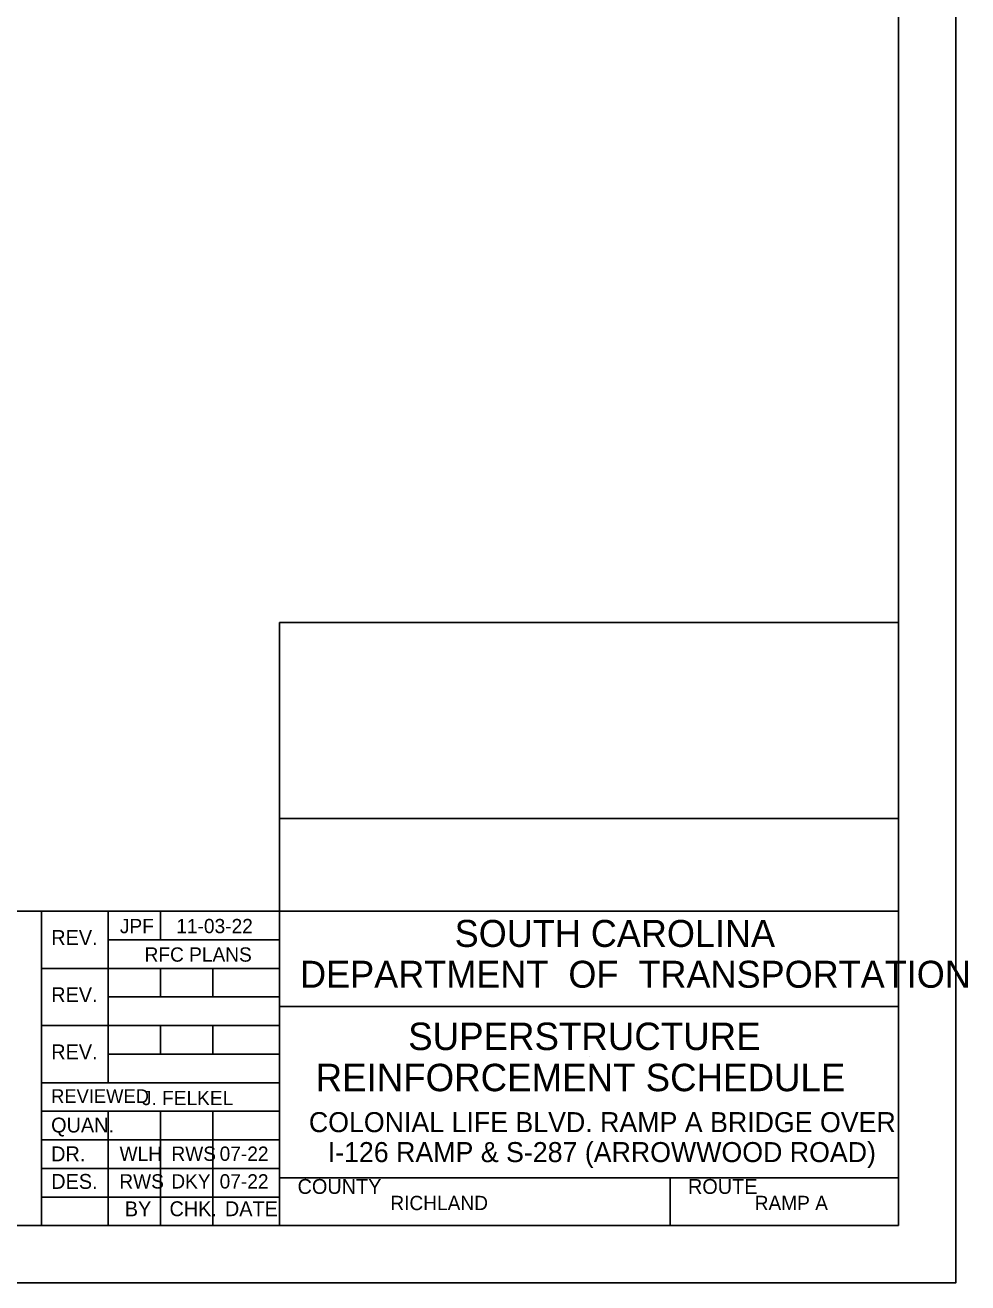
# Model space of a CAD drawing. Extents: x -125.5 to -89.4, y -5.1 to 16.9.
# Drawn here: x -97.68 to -89.43, y -5.07 to 5.93 of the extents above; entities that cross this region are included whole.
import ezdxf

# ---------------------------------------------------------------- set-up
doc = ezdxf.new("R2010")
doc.units = 0
for name, color, linetype in [('BR_BORDER LINES', 7, 'Continuous'), ('BR_TEXT', 7, 'Continuous'), ('Level 31', 7, 'Continuous')]:
    doc.layers.add(name, color=color, linetype=linetype)

msp = doc.modelspace()

# ---------------------------------------------------------------- linework, layer by layer
at = {"layer": 'BR_BORDER LINES'}
for p, q in [((-90.033, -4.566), (-90.033, 16.434)), ((-95.45, -4.566), (-95.45, 0.71)), ((-95.45, 0.71), (-90.033, 0.71)), ((-95.45, -1.004), (-90.033, -1.004)), ((-102.899, -1.816), (-97.534, -1.816)), ((-97.534, -4.566), (-97.534, -1.816)), ((-97.534, -1.816), (-90.033, -1.816)), ((-96.95, -1.816), (-96.95, -3.316)), ((-96.492, -2.066), (-96.492, -1.816)), ((-96.95, -2.066), (-95.45, -2.066)), ((-97.534, -2.316), (-95.45, -2.316)), ((-96.492, -2.566), (-96.492, -2.316)), ((-96.034, -2.566), (-96.034, -2.316)), ((-96.95, -2.566), (-95.45, -2.566)), ((-95.45, -2.649), (-95.45, -2.649)), ((-95.45, -2.649), (-90.033, -2.649)), ((-97.534, -2.816), (-95.45, -2.816)), ((-96.492, -3.066), (-96.492, -2.816)), ((-96.034, -3.066), (-96.034, -2.816)), ((-96.95, -3.066), (-95.45, -3.066)), ((-97.534, -3.316), (-95.45, -3.316)), ((-97.534, -3.566), (-95.45, -3.566)), ((-96.95, -3.566), (-96.95, -4.566)), ((-96.492, -3.566), (-96.492, -4.566)), ((-96.034, -3.566), (-96.034, -4.566)), ((-97.534, -3.816), (-95.45, -3.816)), ((-97.534, -4.066), (-95.45, -4.066)), ((-95.45, -4.149), (-90.033, -4.149)), ((-95.353, -4.149), (-90.033, -4.149)), ((-92.033, -4.566), (-92.033, -4.149)), ((-97.534, -4.316), (-95.45, -4.316)), ((-123.699, -4.566), (-90.033, -4.566))]:
    msp.add_line(p, q, dxfattribs=at)
at = {"layer": 'Level 31'}
msp.add_line((-92.742, -3.09), (-92.742, -3.09), dxfattribs=at)
msp.add_line((-92.742, -3.09), (-92.742, -3.09), dxfattribs=at)
msp.add_lwpolyline([(-125.533, 16.934), (-125.533, -5.066), (-89.533, -5.066), (-89.533, 16.934)], dxfattribs=at)

# ---------------------------------------------------------------- texts
at = {"layer": 'BR_TEXT'}
for s, height, p in [('JPF', 0.125, (-96.848, -2.008)), ('11-03-22', 0.125, (-96.354, -2.008)), ('SOUTH CAROLINA', 0.23587, (-93.918, -2.128)), ('REV.', 0.13, (-97.449, -2.111)), ('RFC PLANS', 0.125, (-96.632, -2.257)), ('DEPARTMENT  OF  TRANSPORTATION', 0.23587, (-95.271, -2.485)), ('REV.', 0.13, (-97.449, -2.611)), ('SUPERSTRUCTURE  ', 0.24, (-94.325, -3.03)), ('REV.', 0.13, (-97.449, -3.111)), ('REINFORCEMENT SCHEDULE', 0.24, (-95.135, -3.39)), ('REVIEWED', 0.12, (-97.45, -3.493)), ('J. FELKEL', 0.125, (-96.655, -3.512)), ('QUAN.', 0.13, (-97.45, -3.751)), ('COLONIAL LIFE BLVD. RAMP A BRIDGE OVER', 0.175, (-95.194, -3.748)), ('I-126 RAMP & S-287 (ARROWWOOD ROAD)', 0.175, (-95.029, -4.01)), ('DR.', 0.13, (-97.45, -4.003)), ('WLH', 0.125, (-96.851, -3.999)), ('RWS', 0.125, (-96.397, -3.999)), ('07-22', 0.125, (-95.975, -3.999)), ('DES.', 0.13, (-97.449, -4.244)), ('RWS', 0.125, (-96.853, -4.241)), ('DKY', 0.125, (-96.398, -4.241)), ('07-22', 0.125, (-95.975, -4.241)), ('COUNTY', 0.13, (-95.293, -4.288)), ('ROUTE', 0.13, (-91.876, -4.288)), ('BY', 0.13, (-96.805, -4.484)), ('CHK.', 0.13, (-96.414, -4.483)), ('DATE', 0.13, (-95.929, -4.483)), ('RICHLAND', 0.125, (-94.481, -4.43)), ('RAMP A', 0.125, (-91.292, -4.43))]:
    msp.add_text(s, height=height, dxfattribs=at).set_placement(p)

doc.saveas('drawing.dxf')
